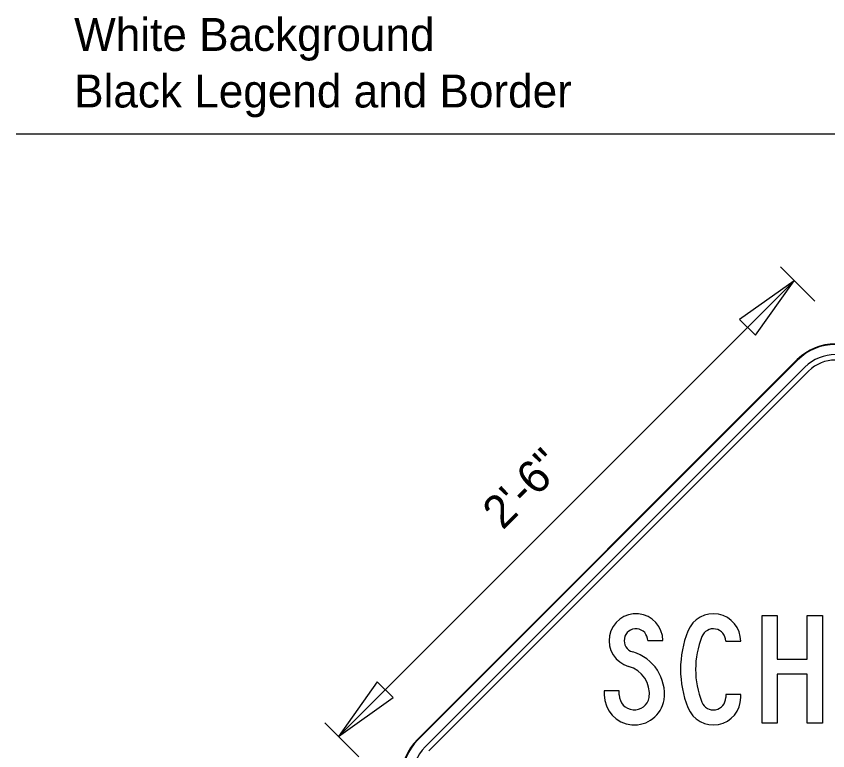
# Model space of a CAD drawing. Extents: x 0 to 770, y 0 to 495.
# Drawn here: x 0 to 86.1, y 264.5 to 342.5 of the extents above; entities that cross this region are included whole.
import ezdxf

# ---------------------------------------------------------------- set-up
doc = ezdxf.new("R2010")
doc.units = 0
for name, color, linetype in [('Dimension', 7, 'Continuous'), ('GSBWFill', 7, 'Continuous'), ('GSColorFill', 7, 'Continuous'), ('GSDims', 7, 'Continuous'), ('GSOutline', 7, 'Continuous'), ('SheetLines_dp', 7, 'Continuous'), ('TextStructures', 7, 'Continuous')]:
    doc.layers.add(name, color=color, linetype=linetype)

msp = doc.modelspace()

# ---------------------------------------------------------------- linework, layer by layer
at = {"layer": 'Dimension'}
for points in [[(82.559, 314.423), (76.757, 310.302), (78.438, 308.621)], [(34.192, 266.056), (39.994, 270.177), (38.313, 271.859)]]:
    msp.add_lwpolyline(points, close=True, dxfattribs=at)
at = {"layer": 'GSBWFill'}
for p, q in [((82.882, 306.04), (42.576, 265.734)), ((83.688, 305.234), (43.382, 264.928)), ((43.785, 264.525), (84.091, 304.831)), ((67.019, 276.216), (68.615, 276.216)), ((75.284, 276.159), (76.88, 276.159)), ((63.998, 270.459), (63.998, 270.887))]:
    msp.add_line(p, q, dxfattribs=at)
msp.add_lwpolyline([(79.16, 278.867), (80.756, 278.867), (80.756, 274.25), (83.948, 274.25), (83.948, 278.867), (85.544, 278.867), (85.544, 267.467), (83.948, 267.467), (83.948, 272.654), (80.756, 272.654), (80.756, 267.467), (79.16, 267.467)], close=True, dxfattribs=at)
for points in [[(63.998, 270.887), (62.402, 270.887), (62.402, 270.459)], [(76.88, 270.174), (76.88, 270.488), (75.284, 270.488), (75.284, 270.174)]]:
    msp.add_lwpolyline(points, dxfattribs=at)
for centre, radius, start, end in [((86.912, 302.009), 5.7, 45, 135), ((86.912, 302.009), 4.56, 45, 135), ((86.912, 302.009), 3.99, 45, 135), ((65.765, 276.216), 2.85, 0, 254.22594), ((65.765, 276.216), 1.254, 0, 254.22594), ((64.169, 270.566), 4.617, 352.12977, 74.22594), ((64.169, 270.566), 3.021, 352.58042, 74.22594), ((65.594, 270.459), 3.192, 180, 350.53133), ((65.594, 270.459), 1.596, 180, 349.78566), ((46.607, 261.703), 5.7, 135, 225), ((46.607, 261.703), 4.56, 135, 225)]:
    msp.add_arc(centre, radius, start, end, dxfattribs=at)
for centre, major_axis, start_param, end_param in [((73.973, 276.159), (0, 2.907), 4.712389, 7.477539), ((73.973, 276.159), (0, 1.311), 4.712389, 7.477539), ((81.543, 273.167), (0, 11.047), 1.194353, 1.947239), ((81.543, 273.167), (0, 9.451), 1.194353, 1.947239), ((73.973, 270.174), (0, 2.907), 1.947239, 4.712389), ((73.973, 270.174), (0, 1.311), 1.947239, 4.712389)]:
    msp.add_ellipse(centre, major_axis=major_axis, ratio=0.999991, start_param=start_param, end_param=end_param, dxfattribs=at)
at = {"layer": 'GSColorFill'}
for p, q in [((82.882, 306.04), (42.576, 265.734)), ((82.882, 306.04), (42.576, 265.734)), ((42.616, 265.694), (82.922, 305.999)), ((83.688, 305.234), (43.382, 264.928)), ((43.785, 264.525), (84.091, 304.831)), ((67.019, 276.216), (68.615, 276.216)), ((75.284, 276.159), (76.88, 276.159)), ((63.998, 270.459), (63.998, 270.887))]:
    msp.add_line(p, q, dxfattribs=at)
msp.add_lwpolyline([(79.16, 278.867), (80.756, 278.867), (80.756, 274.25), (83.948, 274.25), (83.948, 278.867), (85.544, 278.867), (85.544, 267.467), (83.948, 267.467), (83.948, 272.654), (80.756, 272.654), (80.756, 267.467), (79.16, 267.467)], close=True, dxfattribs=at)
for points in [[(63.998, 270.887), (62.402, 270.887), (62.402, 270.459)], [(76.88, 270.174), (76.88, 270.488), (75.284, 270.488), (75.284, 270.174)]]:
    msp.add_lwpolyline(points, dxfattribs=at)
for centre, radius, start, end in [((86.912, 302.009), 5.7, 45, 135), ((86.912, 302.009), 5.7, 45, 135), ((86.912, 302.009), 5.643, 45, 135), ((86.912, 302.009), 4.56, 45, 135), ((86.912, 302.009), 3.99, 45, 135), ((65.765, 276.216), 2.85, 0, 254.22594), ((65.765, 276.216), 1.254, 0, 254.22594), ((64.169, 270.566), 4.617, 352.12977, 74.22594), ((64.169, 270.566), 3.021, 352.58042, 74.22594), ((65.594, 270.459), 3.192, 180, 350.53133), ((65.594, 270.459), 1.596, 180, 349.78566), ((46.607, 261.703), 5.7, 135, 225), ((46.607, 261.703), 5.7, 135, 225), ((46.607, 261.703), 5.643, 135, 225), ((46.607, 261.703), 4.56, 135, 225)]:
    msp.add_arc(centre, radius, start, end, dxfattribs=at)
for centre, major_axis, start_param, end_param in [((73.973, 276.159), (0, 2.907), 4.712389, 7.477539), ((73.973, 276.159), (0, 1.311), 4.712389, 7.477539), ((81.543, 273.167), (0, 11.047), 1.194353, 1.947239), ((81.543, 273.167), (0, 9.451), 1.194353, 1.947239), ((73.973, 270.174), (0, 2.907), 1.947239, 4.712389), ((73.973, 270.174), (0, 1.311), 1.947239, 4.712389)]:
    msp.add_ellipse(centre, major_axis=major_axis, ratio=0.999991, start_param=start_param, end_param=end_param, dxfattribs=at)
at = {"layer": 'GSDims'}
for p, q in [((84.736, 312.247), (81.108, 315.874)), ((34.192, 266.056), (82.559, 314.423)), ((36.369, 263.88), (32.741, 267.507))]:
    msp.add_line(p, q, dxfattribs=at)
at = {"layer": 'GSOutline'}
for p, q in [((82.882, 306.04), (42.576, 265.734)), ((83.688, 305.234), (43.382, 264.928)), ((84.091, 304.831), (43.785, 264.525)), ((67.019, 276.216), (68.615, 276.216)), ((75.284, 276.159), (76.88, 276.159)), ((63.998, 270.459), (63.998, 270.887))]:
    msp.add_line(p, q, dxfattribs=at)
msp.add_lwpolyline([(79.16, 278.867), (80.756, 278.867), (80.756, 274.25), (83.948, 274.25), (83.948, 278.867), (85.544, 278.867), (85.544, 267.467), (83.948, 267.467), (83.948, 272.654), (80.756, 272.654), (80.756, 267.467), (79.16, 267.467)], close=True, dxfattribs=at)
for points in [[(63.998, 270.887), (62.402, 270.887), (62.402, 270.459)], [(76.88, 270.174), (76.88, 270.488), (75.284, 270.488), (75.284, 270.174)]]:
    msp.add_lwpolyline(points, dxfattribs=at)
for centre, radius, start, end in [((86.912, 302.009), 5.7, 45, 135), ((86.912, 302.009), 4.56, 45, 135), ((86.912, 302.009), 3.99, 45, 135), ((65.765, 276.216), 2.85, 0, 254.22594), ((65.765, 276.216), 1.254, 0, 254.22594), ((64.169, 270.566), 4.617, 352.12977, 74.22594), ((64.169, 270.566), 3.021, 352.58042, 74.22594), ((65.594, 270.459), 3.192, 180, 350.53133), ((65.594, 270.459), 1.596, 180, 349.78566), ((46.607, 261.703), 5.7, 135, 225), ((46.607, 261.703), 4.56, 135, 225)]:
    msp.add_arc(centre, radius, start, end, dxfattribs=at)
for centre, major_axis, start_param, end_param in [((73.973, 276.159), (0, 2.907), 4.712389, 7.477539), ((73.973, 276.159), (0, 1.311), 4.712389, 7.477539), ((81.543, 273.167), (0, 11.047), 1.194353, 1.947239), ((81.543, 273.167), (0, 9.451), 1.194353, 1.947239), ((73.973, 270.174), (0, 2.907), 1.947239, 4.712389), ((73.973, 270.174), (0, 1.311), 1.947239, 4.712389)]:
    msp.add_ellipse(centre, major_axis=major_axis, ratio=0.999991, start_param=start_param, end_param=end_param, dxfattribs=at)
at = {"layer": 'SheetLines_dp'}
msp.add_line((0, 330), (770, 330), dxfattribs=at)

# ---------------------------------------------------------------- texts
at = {"layer": 'TextStructures'}
for s, p in [('White Background', (6.145, 338.805)), ('Black Legend and Border', (6.145, 332.805))]:
    msp.add_text(s, height=3.5, dxfattribs=at).set_placement(p)
msp.add_text('2\'-6"', height=3.5, rotation=45, dxfattribs=at).set_placement((51.636, 287.871))

doc.saveas('drawing.dxf')
